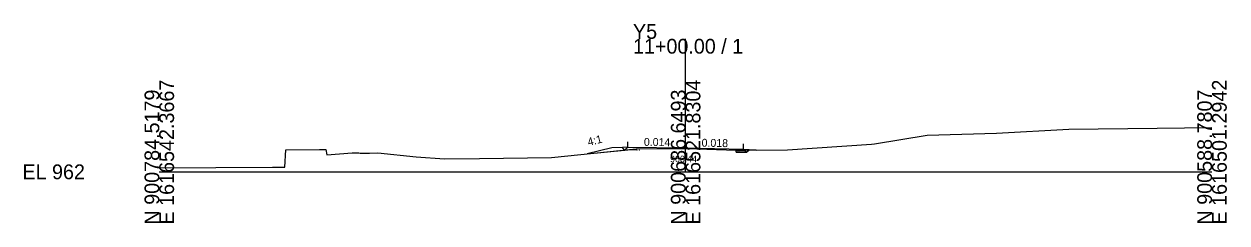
# Model space of a CAD drawing. Extents: x -26 to 1403, y -10 to 4517.
# Drawn here: x -25.7 to 202.8, y 990.3 to 1028 of the extents above; entities that cross this region are included whole.
import ezdxf

# ---------------------------------------------------------------- set-up
doc = ezdxf.new("R2010")
doc.units = 0
for name, color, linetype in [('Exist Cross Section Cell', 7, 'Continuous'), ('Exist XS Center Line Elevation Label', 7, 'Continuous'), ('Exist XS Ground Line', 7, 'Continuous'), ('Prop XS Ditch Slope Text', 7, 'Continuous'), ('Prop XS Dump Level', 7, 'Continuous'), ('Prop XS Earthwork Shape', 7, 'Continuous'), ('Prop XS EOT Tick Mark', 7, 'Continuous'), ('Prop XS Finish Grade', 7, 'Continuous'), ('Prop XS Finish Grade Earthwork', 7, 'Continuous'), ('Prop XS Finish Grade Pavement', 7, 'Continuous'), ('Prop XS Pvmt Edge Slope', 7, 'Continuous'), ('Prop XS SE Text', 7, 'Continuous'), ('Prop XS Subgrade Earthwork', 7, 'Continuous')]:
    doc.layers.add(name, color=color, linetype=linetype)

msp = doc.modelspace()

# ---------------------------------------------------------------- linework, layer by layer
at = {"layer": 'Exist Cross Section Cell'}
for p, q in [((100, 1000), (100, 1025.22)), ((0, 1000), (100, 1000)), ((100, 1000), (200, 1000))]:
    msp.add_line(p, q, dxfattribs=at)
at = {"layer": 'Exist XS Ground Line'}
for p, q in [((159.09, 1007.36), (172.79, 1008.11)), ((172.79, 1008.11), (189.56, 1008.26)), ((189.56, 1008.26), (200, 1008.41)), ((135.89, 1005.3), (145.9, 1006.96)), ((145.9, 1006.96), (159.09, 1007.36)), ((23.88, 1000.87), (24.07, 1004.2)), ((24.07, 1004.2), (30.42, 1004.21)), ((30.42, 1004.21), (31.65, 1004.22)), ((31.65, 1004.22), (31.84, 1003.23)), ((31.84, 1003.23), (36.62, 1003.58)), ((36.62, 1003.58), (37.91, 1003.62)), ((37.91, 1003.62), (38.14, 1003.56)), ((38.14, 1003.56), (39.91, 1003.55)), ((39.91, 1003.55), (41.53, 1003.57)), ((41.53, 1003.57), (48.83, 1002.85)), ((74.5, 1002.69), (90.6, 1004.34)), ((90.6, 1004.34), (100, 1004.44)), ((100, 1004.44), (100.3, 1004.44)), ((100.3, 1004.44), (109.59, 1004.1)), ((109.59, 1004.1), (119.36, 1004.19)), ((119.36, 1004.19), (135.34, 1005.24)), ((135.34, 1005.24), (135.89, 1005.3)), ((48.83, 1002.85), (54.2, 1002.46)), ((54.2, 1002.46), (60.84, 1002.51)), ((60.84, 1002.51), (74.5, 1002.69)), ((0, 1000.74), (21.5, 1000.87)), ((21.5, 1000.87), (23.88, 1000.87))]:
    msp.add_line(p, q, dxfattribs=at)
at = {"layer": 'Prop XS Dump Level'}
for p, q in [((89, 1004.68), (100, 1004.52)), ((100, 1004.52), (111, 1004.32))]:
    msp.add_line(p, q, dxfattribs=at)
at = {"layer": 'Prop XS Earthwork Shape'}
for points in [[(85.99, 1004.56), (81.32, 1003.39), (88.37, 1004.11), (88, 1004.64)], [(89, 1004.09), (88.4, 1004.08), (88.45, 1004.12), (90.6, 1004.34), (90.6, 1004.14)], [(109.59, 1003.74), (109.59, 1004.1), (111.21, 1004.11), (111.58, 1003.74), (111, 1003.74), (110.45, 1003.74)], [(111.21, 1004.11), (111.58, 1003.74), (111.98, 1004.12)], [(112.1, 1004.24), (113.43, 1004.13), (111.98, 1004.12)]]:
    msp.add_lwpolyline(points, close=True, dxfattribs=at)
at = {"layer": 'Prop XS EOT Tick Mark'}
for p, q in [((89, 1004.68), (89, 1005.68)), ((111, 1004.32), (111.02, 1005.32))]:
    msp.add_line(p, q, dxfattribs=at)
at = {"layer": 'Prop XS Finish Grade'}
for p, q in [((89, 1004.68), (88, 1004.64)), ((111, 1004.32), (112.1, 1004.24))]:
    msp.add_line(p, q, dxfattribs=at)
at = {"layer": 'Prop XS Finish Grade Earthwork'}
for p, q in [((85.99, 1004.56), (81.32, 1003.39)), ((88, 1004.64), (85.99, 1004.56)), ((112.1, 1004.24), (113.43, 1004.13))]:
    msp.add_line(p, q, dxfattribs=at)
at = {"layer": 'Prop XS Finish Grade Pavement'}
for p, q in [((89, 1004.68), (100, 1004.52)), ((100, 1004.52), (111, 1004.32))]:
    msp.add_line(p, q, dxfattribs=at)
at = {"layer": 'Prop XS Pvmt Edge Slope'}
for p, q in [((89, 1004.68), (88.4, 1004.08)), ((111, 1004.32), (111.58, 1003.74))]:
    msp.add_line(p, q, dxfattribs=at)
at = {"layer": 'Prop XS Subgrade Earthwork'}
for p, q in [((88.4, 1004.08), (88, 1004.64)), ((89, 1004.09), (88.4, 1004.08)), ((90.6, 1004.14), (89, 1004.09)), ((90.6, 1004.14), (90.6, 1004.34)), ((109.59, 1003.74), (109.59, 1004.1)), ((109.59, 1003.74), (111.58, 1003.74)), ((110.45, 1003.74), (111, 1003.74)), ((112.1, 1004.24), (111.58, 1003.74))]:
    msp.add_line(p, q, dxfattribs=at)

# ---------------------------------------------------------------- texts
at = {"layer": 'Exist Cross Section Cell'}
for s, p in [('Y5', (90, 1025.22)), ('11+00.00 / 1', (90, 1022.42)), ('EL 962', (-26, 998.6))]:
    msp.add_text(s, height=2.8, dxfattribs=at).set_placement(p)
for s, p in [('E 1616542.3667', (2.8, 990)), ('E 1616521.8304', (102.8, 990)), ('E 1616501.2942', (202.8, 990)), ('N 900784.5179', (0, 990)), ('N 900686.6493', (100, 990)), ('N 900588.7807', (200, 990))]:
    msp.add_text(s, height=2.8, rotation=90, dxfattribs=at).set_placement(p)
at = {"layer": 'Exist XS Center Line Elevation Label'}
msp.add_text('966.44', height=1.25, dxfattribs=at).set_placement((97.04, 1001.82))
at = {"layer": 'Prop XS Ditch Slope Text'}
msp.add_text('4:1', height=1.5, rotation=14.0362, dxfattribs=at).set_placement((81.56, 1004.89))
at = {"layer": 'Prop XS Dump Level'}
for p in [(90.6, 1004.04), (109.59, 1003.8)]:
    msp.add_text('Eop', height=0.3, dxfattribs=at).set_placement(p)
at = {"layer": 'Prop XS SE Text'}
for s, rotation, p in [('0.014', 359.1986, (92.06, 1004.93)), ('0.018', 358.9688, (103.02, 1004.77))]:
    msp.add_text(s, height=1.5, rotation=rotation, dxfattribs=at).set_placement(p)

doc.saveas('drawing.dxf')
